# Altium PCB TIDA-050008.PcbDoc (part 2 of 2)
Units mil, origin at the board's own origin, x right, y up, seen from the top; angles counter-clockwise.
Board outline 3500 x 2500 mil, 4 copper layers (Top Layer, Signal Layer 1, Signal Layer 2, Bottom Layer), stack 38.4 mil thick; 136 components, 48 nets, 303 pads, 230 vias.
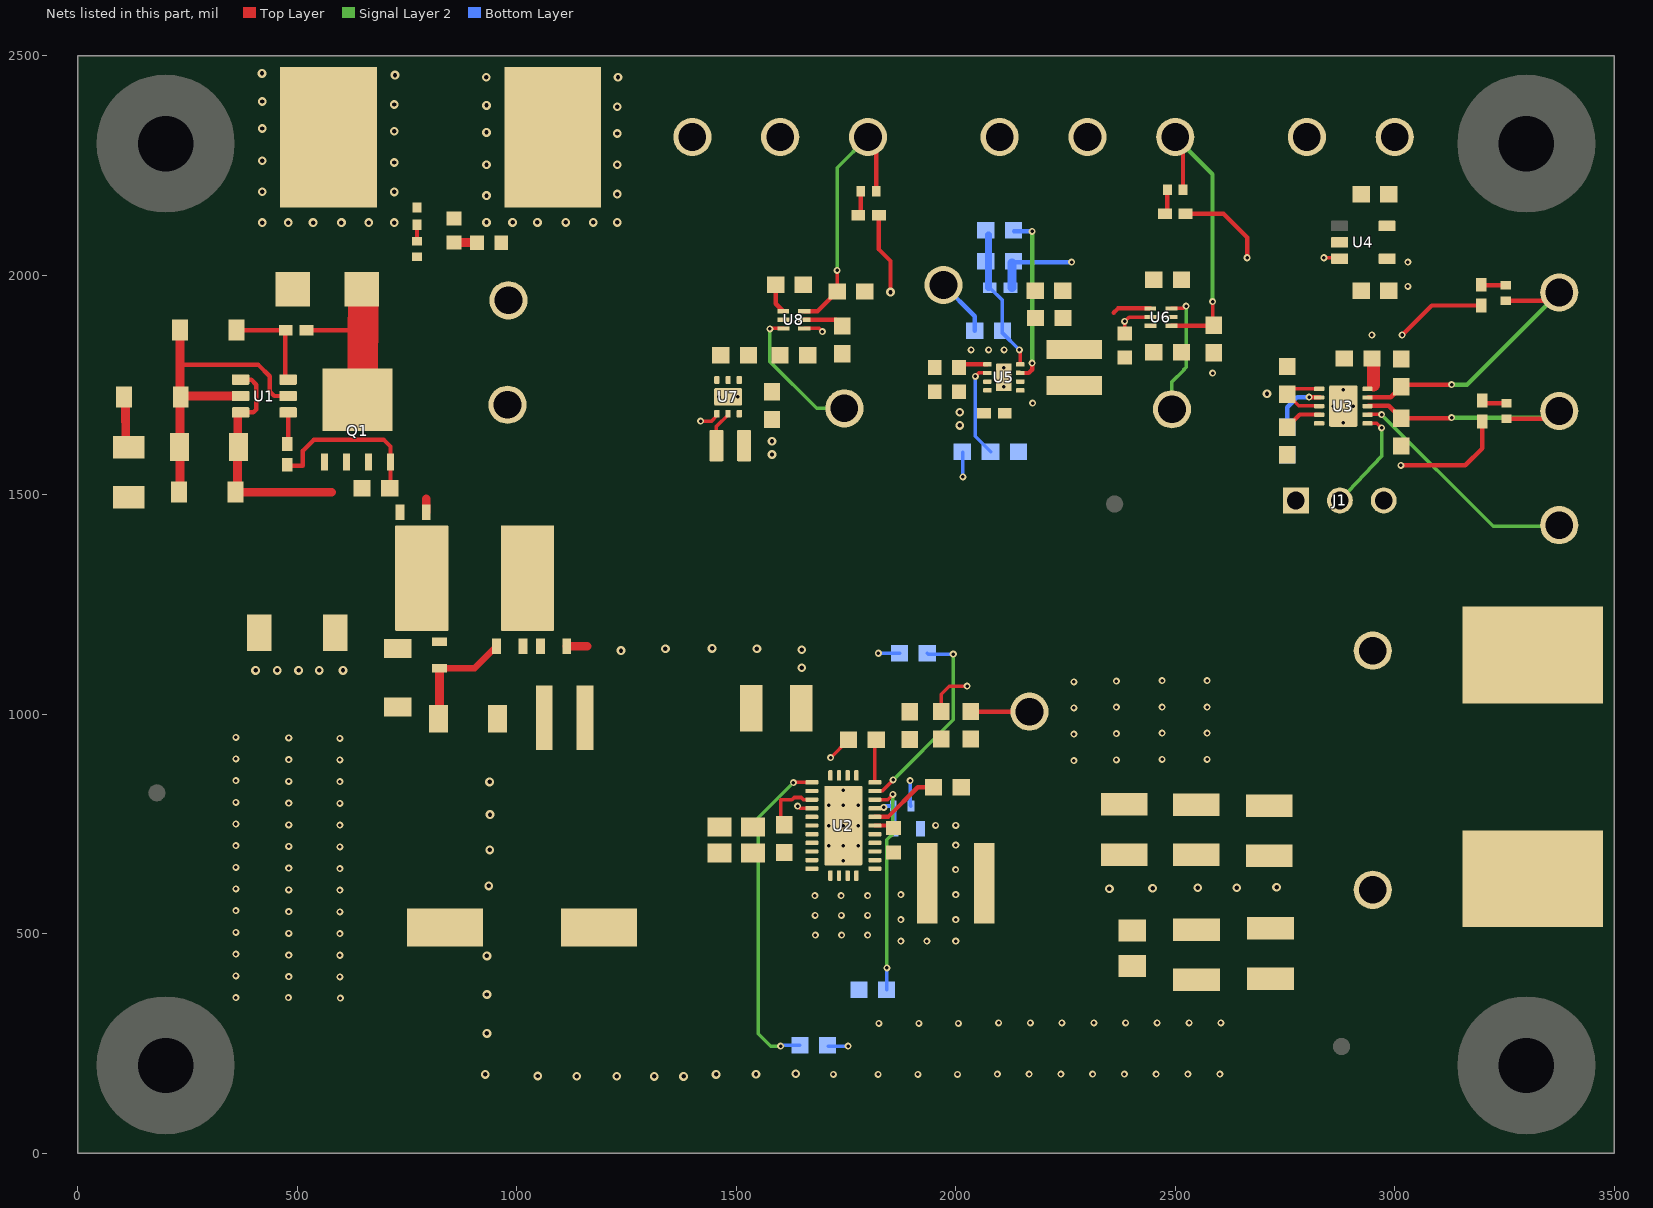
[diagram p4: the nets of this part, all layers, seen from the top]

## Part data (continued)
TP4 TP5: library part CMP-0055149-1, "Test Point, Multipurpose, White, TH", Color=White, Manufacturer=Keystone, PartNumber=5012, Supplier Part Number 1=36-5012-ND
TP6 TP13 TP17: library part CMP-0055151-1, "Test Point, Multipurpose, Yellow, TH", Color=Yellow, Manufacturer=Keystone, PartNumber=5014, Supplier Part Number 1=36-5014-ND
TP7 TP10 TP12 TP16 TP19: library part CMP-0055148-1, "Test Point, Multipurpose, Black, TH", Color=Black, Manufacturer=Keystone, PartNumber=5011, Supplier Part Number 1=36-5011-ND
TP8: library part CMP-0055150-1, "Test Point, Multipurpose, Orange, TH", Color=Orange, Manufacturer=Keystone, PartNumber=5013, Supplier Part Number 1=36-5013-ND
U1: library part CMP-0080758-2, "Automotive 40-V, microPower, Push-Pull Comparator with Shutdown, DBV0006A (SOT-23-6)", Alternate Manufacturer="Texas Instruments"
U2: library part CMP-0013936-4, "Automotive 3.5V to 36V 5A Synchronous Step-Down Voltage Regulator, RNP0030A (WQFN-30)", Alternate Manufacturer="Texas Instruments", Alternate PartNumber=LM73605QRNPTQ1
U3: library part CMP-0081417-2, "Automotive Precision Voltage Supervisor With Programmable Window Watchdog Timer, DRC0010R (VSON-10)", Alternate Manufacturer="Texas Instruments", Operating Temperature Range="-40 to 125 C", Rating=Automotive
U4: library part CMP-0081400-1, "Automotive SOT23 Precision Low Dropout Voltage Reference, DBV0005A (SOT-23-5)", Alternate Manufacturer="Texas Instruments", Alternate PartNumber=LM4132AQ1MFR2.5, Operating Temprature Range="-40 to 125 C", Rating=Automotive
U5: library part CMP-0074019-3, "3MHz, 2A Automotive Step-Down Converter in 2x2 SON Package, DSG0008A (WSON-8)", Alternate Manufacturer="Texas Instruments"
U6: library part CMP-0081404-1, "Automotive High-Accuracy Window Supervisor With Reset Time Delay and Manual Reset, DSE0006A (WSON-6)", Alternate Manufacturer="Texas Instruments"
U7: library part CMP-0065188-6, "3.5-MHz High Efficiency Step-Up Converter, DRV0006A (WSON-6)", Alternate Manufacturer="Texas Instruments"
U8: library part CMP-0081405-1, "Automotive Low-Quiescent-Current 1% Accurate Supervisor With Programmable Delay, DSE0006A (WSON-6)", Alternate Manufacturer="Texas Instruments", Operating Temprature Range="-40 to 125 C", Rating=Automotive
ZZ1: library part AssemblyNoteLabel
ZZ2 ZZ3 ZZ4: library part AssemblyNote

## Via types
v1: diameter 16, hole 8, Top Layer to Bottom Layer, 129 vias
v2: diameter 20, hole 10, Top Layer to Bottom Layer, 70 vias
v3: diameter 19.68, hole 8, Top Layer to Bottom Layer, 15 vias
v4: diameter 16, hole 8, Top Layer to Bottom Layer, tented both sides, 11 vias
v5: diameter 19.68, hole 7.87, Top Layer to Bottom Layer, 4 vias
v6: diameter 16/16/16/16 (per signal layer), hole 8, Top Layer to Bottom Layer, 1 vias

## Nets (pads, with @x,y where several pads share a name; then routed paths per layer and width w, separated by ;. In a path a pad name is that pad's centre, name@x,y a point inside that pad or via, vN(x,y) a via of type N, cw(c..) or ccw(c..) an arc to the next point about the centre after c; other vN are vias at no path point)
1.2RESET: D10.1 R10.1 TP13.1 U6.4 | length 684.6
  Top Layer w8: v1(2585,1940) 2585,1888.94 R10.1@2587,1886.94
  Top Layer w10: U6.4@2491.22,1885.16 R10.1@2586.42,1885.16 ; TP13.1@2500,2315 2517.72,2297.29 D10.1@2517.72,2195
  Signal Layer 2 w10: TP13.1@2500,2315 2585,2230 v1@2585,1942
3.3RESET: D8.1 R6.1 TP6.1 U3.9 | length 663.5
  Top Layer w10: U3.9@2940.12,1722.29 2991.18,1722.29 R6.1@3015,1746.11 3019.79,1750.9 v1(3129.77,1750.9) ; D8.1@3252.59,1942.06 3355.93,1942.06 TP6.1@3374.77,1960.9
  Signal Layer 2 w10: v1(3129.77,1750.9) 3164.77,1750.9 TP6.1@3374.77,1960.9
5.0RESET: D7.1 R12.1 TP17.1 U8.6 | length 605.3
  Top Layer w8: R12.1@1730,1963.22 v1(1730,2011)
  Top Layer w10: U8.6@1654.97,1918.27 1685.04,1918.27 R12.1@1729.85,1963.07 ; TP17.1@1800,2315 1819.06,2295.94 D7.1@1819.06,2191.77
  Signal Layer 2 w8: v1(1730,2011) 1730,2245 TP17.1@1800,2315
+1.2V: C6.1 C20.1 C21.1 C22.1 L2.2 R8.2 TP11.1 U6.1 | length 274.6
  Top Layer w10: 2360,1915 2369.53,1924.53 U6.1@2443.19,1924.53
  Bottom Layer w10: R8.2@2133.7,2030 v1(2264,2030)
  Bottom Layer w20: C20.1@2128.3,1971.46 R8.2@2128.3,2028.59
+2.5Vref: C15.1 TP9.1 U4.5
+3.3V: C11.1 C13.1 C16.1 C17.1 C18.1 C19.1 C23.1 C26.1 C28.1 CFF.1 CO1.1 CO2.1 CO3.1 CO4.1 CO5.1 CO.2 J1.1 L1.2 L3.1 P3.1 R5.2 R6.2 R7.2 R10.2 R11.2 R12.2 R15.1 R16.1 R17.1 R18.1 Rbias1.2 RFBT.2 RPG.2 TP18.1 U3.1 U3.3 U3.10 U4.3 U4.4 U5.5 U5.7 U5.8 U6.2 U7.4 U7.6 U8.4 | length 1595.7
  Top Layer w8: v1(1419,1668) 1443.93,1668 U7.4@1455.75,1679.82 ; U8.4@1654.97,1878.9 1689.22,1878.9 v1(1696.34,1871.77) ; RFBT.2@1967,1006.5 1967,1046 1985,1064 v1(2026,1064) ; C23.1@2385,1871.5 v1(2385,1895) 2394.84,1904.85 U6.2@2443.98,1904.85 ; C11.1@2755,1729.16 2781.55,1702.6 U3.3@2829.88,1702.6 ; C11.1@2767.82,1741.97 U3.1@2829.88,1741.97 ; v1(2838.91,2040) 2871.09,2040 U4.3@2873.3,2037.79
  Top Layer w10: R18.1@1824.97,2136.77 1824.97,2059.03 1851.34,2032.66 v2(1851.34,1961.77) ; C18.1@2014.35,1797.15 U5.5@2072.15,1797.15 ; R17.1@2523.62,2140 2610,2140 2664,2086 v1(2664,2040) ; v1(3014,1567) 3161,1567 3199.77,1605.77 R16.1@3199.77,1667.28 ; v1(3017,1864) 3084.15,1931.15 R15.1@3197.59,1931.15
  Top Layer w30: 2951.73,1750.52 C13.1@2951.73,1800.34
  Bottom Layer w8: RPG.2@1709.48,244 v1(1754.99,244) ; v1(1895.99,849) 1895.99,793 Rbias1.2@1897.99,791 ; v1(2016,1541) R11.2@2016,1596.62
  other v1: 2585,1777 2948,1864 3030,1975 3030,2030
  other v2: 2350,602.5 2448.5,603.5 2551.5,605 2640,605 2731,606 1581.34,1591.77 1581.34,1621.77 2009,1658 2009,1688 2709,1730
+5V: C9.2 C29.1 TP15.1 U7.2 U7.3 U8.1 | length 66.9
  Top Layer w10: C29.1@1589.85,1978.07 1589.85,1935.35 U8.1@1606.93,1918.27
AGND: CSS.2 NTGND1.2 RFBB.1 U2.19 | length 140
  Top Layer w8: v6(1639.99,790.5) 1644.62,785.87 U2.19@1672.14,785.87 ; v1(1715,901) RFBB.1@1755.68,942.2
  Bottom Layer w8: v1(1824,1139) CSS.2@1871.99,1139
AGND2: NTGND2.2 R9.1 U5.3 | length 385.4
  Top Layer w10: U5.3@2148,1777.47 2166.47,1777.47 2174,1785 v1(2174,1800)
  Signal Layer 2 w10: v1(2174,1800) v1(2174,2100)
  Bottom Layer w10: R9.1@2132.71,2100 v1(2174,2100)
BATT_SENS_PCH: D3.1 R1.1 U1.3 | length 223.6
  Top Layer w10: D3.1@361.72,1875 472.77,1875 U1.3@472.77,1762.41
BIAS: Cbias1.1 Rbias1.1 U2.8 | length 63.3
  Bottom Layer w8: v1(1835.99,788) 1838.99,791 Rbias1.1@1857.99,791 1860.49,788.5 Cbias1.1@1860.49,752
CMP_OUT_PCH: R2.1 U1.1 | length 69.8
  Top Layer w10: R2.1@479.13,1617.76 U1.1@479.13,1687.6
CRST: R7.1@2755,1654.1 U3.4 | length 86.8
  Top Layer w10: R7.1@2755,1654.1 2783.82,1682.92 U3.4@2829.88,1682.92
CT1: C10.1 U8.5 | length 72.4
  Top Layer w10: U8.5@1654.97,1898.58 C10.1@1727.33,1898.58
CT2: R7.1@2451.1,1824.85 U6.3
CWD: C12.1 U3.2 | length 129.6
  Top Layer w10: v1@2805.31,1722.29 U3.2@2829.88,1722.29
  Bottom Layer w10: C12.1@2755,1654.1 2755,1699.63 2777.97,1722.6 v1(2805,1722.6)
FB1: CFF.2 R20.2 RFBB.2 RFBT.1 U2.11 | length 98.7
  Top Layer w8: U2.11@1815.84,844.93 RFBB.2@1815.84,939.37 ; CFF.2@1892,939.5 CFF.2@1895,942.5
FB2: C20.2 R8.1 R9.2 R19.2 U5.4 | length 320.9
  Top Layer w8: U5.4@2146.95,1797.15 v1@2146.95,1828.06
  Bottom Layer w8: C20.2@2077.38,1972 2106.5,1942.88 R19.2@2106.5,1874 2106.5,1868.51 v1(2145,1830)
  Bottom Layer w15: C20.2@2074.65,1971.99 R9.2@2074.65,2091.99
FLT_GND_P: C4.2 D3.2 D4.2 D5.2 U1.2 U1.5 | length 788.1
  Top Layer w10: 234,1796 411.38,1795.87 437.25,1770 437.25,1735 447.25,1725 U1.2@472.77,1725
  Top Layer w20: D3.2@232.78,1875 D5.2@233,1505 ; D4.2@235,1725 U1.5@364.5,1725
GND: C1.2 C2.2 C3.2 C6.2 C8.2 C9.1 C10.2 C11.2 C12.2 C13.2 C15.2 C16.2 C17.2 C18.2 C19.2 C21.2 C22.2 C23.2 C25.2 C26.2 C28.2 C29.2 Cbias1.2 Cbulk1.2 CF1.2 CF2.2 CI1.1 CI2.1 CI3.2 CI4.2 CO1.2 CO2.2 CO3.2 CO4.2 CO5.2 CO.1 CVCC.2 D1.2 D6.2 J1.3 NTGND1.1 NTGND2.1 P2.1 P4.1 R3.1 R13.1 R14.1 RT.2 TP7.1 TP10.1 TP12.1 TP16.1 TP19.1 U2.12 U2.13 U2.14 U2.15 U2.17 U2.23 U2.24 U2.25 U2.26 U2.27 U2.28 U2.29 U2.30 U2.31 U3.5 U3.11 U4.2 U5.1 U5.9@2109.55,1767.62 U6.5 U7.1 U7.7@1481.34,1723.07 U8.2 | length 342.9
  Top Layer w8: U6.5@2491.22,1904.85 U6.5@2491.38,1905
  Top Layer w15: C2.2@824.01,1105 904.01,1105 C8.2@954.01,1155
  Top Layer w20: C1.2@794.01,1460 794.01,1490.99 ; CF2.2@824.01,990.04 C2.2@824.01,1105 ; C3.2@1114.01,1155 1160,1155
  other v1: 1721.5,179.5 1823,179.5 1914,179.5 2004,179.5 2095,180 2167,180 2239.5,180 2312,180 2384,180 2456.5,180 2529,180 2601.5,180 1824.99,296 1915.99,296 2005.99,296 2097.49,297 2169.99,297 2241.99,297 2314.49,297 2386.99,297 2458.99,297 2531.49,297 2603.99,297 598,353.5 360,354.5 479.5,354.5 597,401.5 480.5,402.5 360,404 480.5,451.5 597,451 360,453.5 1680.13,497.01 1740.13,497.01 1799.13,497.01 597,500.5 480.5,501 360,503 1679.5,542 1739.5,542 1799,542 480.5,550.5 597,550 360,552.5 1679.13,587.01 1739.13,587.01 1799.13,587.01 597,599.5 480.5,600 360,602 597,648.5 480.5,649.5 360,651 597,698 480.5,699 360,700.5 597,747.5 480.5,748 360,750 480.5,797.5 597,797 360,799.5 597,846.5 480.5,847 360,849 2269,894.5 480.5,896.5 597,896 2366,896 2470,897 2572.5,897 360,898.5 597,945 480.5,946 360,947.5 2269,954.5 2366,956 2470,957 2572.5,957 2269,1014.5 2366,1016 2470,1016.5 2572.5,1016.5 2269,1074 2366,1075.5 2470,1076.5 2572.5,1076.5 2175,1709 2035,1830 2075,1830 2110,1830
  other v2: 1136.51,175.5 1227.51,175.5 1313.01,175 1380.01,175 1048.01,176 928.02,179.5 1454,179.5 1545,180 1635.5,181 931.99,273 931.99,361.5 931.99,449.5 935.99,609 938.49,691 938.99,771.5 937.99,846 405,1100 454.5,1100 503,1100 550,1100 604,1100 1648.99,1106 1237.51,1145 1649,1147 1338.51,1149 1547,1149 1445.01,1150 420,2120 479.5,2120 536,2120 600.5,2120 663,2120 721,2120 420,2190.5 721,2190 721,2257 420,2261 721,2328 420,2334.5 721,2389 420,2396 722.5,2456 419.5,2460
  other v3: 1743.99,665.79 1710.52,700.83 1743.99,700.83 1777.45,700.83 1710.52,746.5 1743.99,746.5 1777.45,746.5 1710.52,792.17 1743.99,792.17 1777.45,792.17 1743.99,827.21 1459.69,1723.07 1503,1723.07 2109.55,1745.97 2109.55,1789.28
  other v4: 1875,483 1934,483 2000,483 1875,532 2000,532.03 1875,589 2000,589 2000,645.97 2000,702 1954,747 2000,747
  other v5: 2883,1664.6 2860.36,1702 2905.64,1702 2883,1739.4
L: L3.2 U7.5 | length 81.7
  Top Layer w8: L3.2@1454.85,1611.77 1454.85,1656.04 U7.5@1481.34,1682.54
LOAD_SENS_PCH: C1.1 C2.1 C4.1 CF1.1 D5.1 D6.1 FB1.1 Q1.1 Q1.2 Q1.3 R4.1 U1.4 U1.6 | length 545.6
  Top Layer w10: U1.6@364.5,1687.6 399.85,1687.6 406.43,1694.18 406.43,1750.83 394.85,1762.41 U1.4@364.5,1762.41
  Top Layer w20: D5.1@363.25,1506 578.25,1506 ; D5.1@364,1505 U1.6@364.5,1687.6
MODE: R11.1 R13.2 U5.6 | length 217.7
  Top Layer w8: v1(2044.55,1769.91) 2052.11,1777.47 U5.6@2072.15,1777.47
  Bottom Layer w8: v1(2044.55,1769.91) 2044.55,1633.08 R13.2@2080,1597.62
MR1: TP3.1 U8.3 | length 319.2
  Top Layer w8: v1@1577.17,1878.9 U8.3@1607.72,1878.9
  Signal Layer 2 w8: v1(1576.34,1878.07) 1576.34,1803.64 1683.22,1696.77 TP3.1@1746.34,1696.77
MR2: TP14.1 U6.6 | length 285.1
  Top Layer w8: U6.6@2491.22,1924.53 2519.53,1924.53 v1(2525,1930)
  Signal Layer 2 w8: TP14.1@2492.6,1694.85 2492.6,1757.09 2520.6,1785.09 2520,1785.69 2525,1790.69 v1(2525,1930)
NetC3_1: C3.1 C8.1 CF2.1 FB1.2 LF1.1
NetC24_1: C24.1 C25.1 | length 52
  Top Layer w20: C25.1@857,2074.44 C24.1@909,2074.44
NetCB_1: CB.1 U2.6 | length 39.2
  Top Layer w10: U2.6@1815.84,746.5 CB.1@1855.06,746.5
NetD2_2: D2.2 R14.2 | length 42.6
  Top Layer w10: D2.2@772.8,2077.59 R14.2@772.8,2120.19
NetD4_1: D4.1 R3.2 | length 109.9
  Top Layer w20: D4.1@108.78,1717.89 R3.2@109,1608
NetD7_2: D7.2 R18.2 | length 49.1
  Top Layer w10: R18.2@1783.63,2142.68 D7.2@1783.63,2191.77
NetD8_2: D8.2 R15.2 | length 54.1
  Top Layer w10: R15.2@3198.49,1977.49 D8.2@3252.59,1977.49
NetD9_2: D9.2 R16.2 | length 49.1
  Top Layer w10: R16.2@3205.68,1708.61 D9.2@3254.77,1708.61
NetD10_2: D10.2 R17.2 | length 49.1
  Top Layer w10: R17.2@2482.28,2145.91 D10.2@2482.28,2195
NetRPG_1: RPG.1 U2.16 | length 754.2
  Top Layer w8: v1(1629.99,844) 1630.91,844.93 U2.16@1672.14,844.93
  Signal Layer 2 w8: v1@1605.49,244 1578.49,244 1550.49,272 1550.49,358 1550.49,764.5 v1(1629.99,844)
  Bottom Layer w8: v1@1605.49,244 1606.99,245.5 RPG.1@1644.99,245.5
  other v1: 1601,244
P_Gate: Q1.4 R2.2 R4.2 | length 364.8
  Top Layer w10: R2.2@479.63,1565.75 512.25,1565.75 512.25,1600 537.25,1625 697.25,1625 712.25,1610 Q1.4@712.25,1574.57 R4.2@712.25,1528.63
RT: RT.1 U2.9 | length 496.9
  Top Layer w8: U2.9@1815.84,805.56 1845.04,805.56 v1(1856.99,817.5)
  Signal Layer 2 w8: v1(1843,422) 1843,714.19 1856.99,728.17 v1(1856.99,817.5)
  Bottom Layer w8: RT.1@1843,372.5 v1(1843,422)
SET1: J1.2 U3.6 | length 237.7
  Top Layer w8: U3.6@2940.12,1663.23 2959.37,1663.23 v1(2970,1652.6)
  Signal Layer 2 w8: J1.2@2875,1487 2970,1587.6 v1(2970,1652.6)
SS/TRK: CSS.1 U2.10 | length 455.9
  Top Layer w8: U2.10@1815.84,825.24 1832.45,825.24 v1(1857.49,850.27)
  Signal Layer 2 w8: v1(1857.49,850.27) 1994.33,987.12 v1(1994.33,1137)
  Bottom Layer w8: v1(1857.49,850.27) v1@1857.72,850.5 ; CSS.1@1934.98,1139 1936.98,1137 v1(1994.33,1137)
SW: CB.2 L1.1 U2.1 U2.2 U2.3 U2.4 U2.5
SW2: L2.1 U5.2
V_CTRL1: R20.1 TP5.1 | length 133.5
  Top Layer w10: R20.1@2034.5,1006 TP5.1@2168,1006
V_CTRL2: R19.1 TP4.1 | length 133.6
  Bottom Layer w10: TP4.1@1972,1978 2043.5,1906.5 R19.1@2043.5,1874
VBATT_PCH: C24.2 D1.1 D2.1 P1.1 Q1.5 R1.2 TP2.1 | length 362.7
  Top Layer w10: R1.2@520.87,1875 648.74,1875
  Top Layer w70: Q1.5@648.74,1728.19 D1.1@650,1963
  other v2: 931,2120.5 990.5,2120.5 1047,2120.5 1111.5,2120.5 1174,2120.5 1229,2120.5 931,2181.5 1229,2185 931,2252 1229,2252 1229,2323 931,2325.5 1229,2384 931,2387 930.5,2451 1230.5,2451
VCC: CVCC.1 U2.7 | length 161.8
  Top Layer w10: U2.7@1815.84,766.19 1845.92,766.19 1913.73,834 CVCC.1@1949.5,834
VIN1: Cbulk1.1 CI1.2 CI2.2 CI3.1 CI4.1 LF1.2 U2.18 U2.20 U2.21 U2.22 | length 136
  Top Layer w8: CI1.2@1608.99,748 1600.99,756 1600.99,805.56 1626.94,805.56 1631.76,810.37 1648.22,810.37 1653.04,805.56 U2.18@1672.14,805.56
WDI: TP1.1 U3.7 | length 539.7
  Top Layer w8: U3.7@2940.12,1682.92 v1@2969.69,1682.92
  Signal Layer 2 w8: v1(2970,1682.6) 3224.3,1428.3 TP1.1@3374.81,1428.3
WDO: D9.1 R5.1 TP8.1 U3.8 | length 557
  Top Layer w10: U3.8@2940.12,1702.6 2986.5,1702.6 R5.1@3015,1674.1 v1@3127.97,1674.1 ; D9.1@3254.77,1673.18 3357.06,1673.18 TP8.1@3374.77,1690.9
  Signal Layer 2 w10: v1(3129.77,1675.9) TP8.1@3359.77,1675.9
pads on no net: FID1.1 FID2.1 FID3.1 H1.1 H2.1 H3.1 H4.1 U2.31A U4.1 U5.9@2109.55,1749.91 U5.9@2109.55,1785.34 U7.7@1463.63,1723.07 U7.7@1499.06,1723.07

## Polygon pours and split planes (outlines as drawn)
+2.5Vref on Top Layer "TOP_LAYER_+2.5VREF_P060" (solid, remove dead copper, pour order 60): 2970,2190 3005,2190 3005,2220 3020,2230 3075,2275 3075,2390 2925,2390 2925,2265 2970,2220
+3.3V on Top Layer "TOP_LAYER_+3.3V_P055" (solid, remove dead copper, pour order 55): 2080,1760 2065,1760 2060,1750 1994.12,1750 1994.12,1645 2080,1645
NetC3_1 on Top Layer "TOP_LAYER_NETC3_1_P057" (solid, remove dead copper, pour order 57): 1005.01,1335 1005.01,1105 935.01,1035 935,899 1074,899 1074,1335
+1.2V on Top Layer "TOP_LAYER_+1.2V_P061" (solid, remove dead copper, pour order 61): 2225,1820 2225,1833.91 2225,2390 2375,2390 2375,1910.82 2325,1860.82 2325,1820
+5V on Top Layer "TOP_LAYER_+5V_P059" (solid, remove dead copper, pour order 59): 1446.34,1751.77 1486.34,1751.77 1486.34,1836.77 1486.34,1886.77 1606.34,1966.77 1671.34,2026.77 1671.34,2390 1531.34,2390 1531.34,2116.77 1446.34,2031.77
VBATT_PCH on Top Layer "TOP_LAYER_VBATT_PCH_P058" (solid, remove dead copper, pour order 58): 905,2530 905,2048 650,2048 650,1820 1060,1820 1255,2015 1255,2530
+3.3V on Top Layer "TOP_LAYER_+3.3V_P062" (solid, remove dead copper, pour order 62): 2043,478.69 2043,709 2934,709 2991.01,766 3474.52,766 3474.52,479.31
SW2 on Top Layer "TOP_LAYER_SW2_P056" (solid, remove dead copper, pour order 56): 2146.95,1762.46 2146.95,1752.46 2180.37,1752.46 2207.37,1729.47 2315,1729.47 2315,1769 2198.02,1769 2180.37,1762.46
SW on Top Layer "TOP_LAYER_SW_P054" (solid, remove dead copper, pour order 54): 1800.61,706 1958,706 1958,538 1913,538 1913,645 1800.61,645
VIN1 on Top Layer "TOP_LAYER_VIN1_P049" (solid, remove dead copper, pour order 49): 1609.5,774.79 1145,774.79 1145,719.5 1609.01,719.5
VIN1 on Top Layer "TOP_LAYER_VIN1_P050" (solid, pour order 50): 1585.61,774.22 1675.77,774.72 1675.77,719.28 1585.61,719.28
GND on Top Layer "TOP_LAYER_GND_P065" (solid, remove dead copper, pour order 65): 20,2480 20,19 3486,19 3486,2480
LOAD_SENS_PCH on Top Layer "TOP_LAYER_LOAD_SENS_PCH_P053" (solid, remove dead copper, pour order 53): 555,1593 555,1131 844,1131 844,1429 843,1430 767.43,1430 744,1453.43 744,1478.68 677.32,1478.68 669,1487 669,1593
VIN1 on Top Layer "TOP_LAYER_VIN1_P052" (solid, remove dead copper, pour order 52): 1138.61,1063 1138.61,473 1224,473 1224,1063
VIN1 on Top Layer "TOP_LAYER_VIN1_P051" (solid, remove dead copper, pour order 51): 1534.35,1063 1156.85,1063 1156.85,968 1533.5,968
GND on Signal Layer 2 "SIGNAL_LAYER_2_GND_P067" (solid, remove dead copper, pour order 67): 0,2500 0,0 3500,0 3500,2500
+3.3V on Signal Layer 2 "SIGNAL_LAYER_2_+3.3V_P064" (solid, remove dead copper, pour order 64): 1389,2058 3145,2058 3145,150 1389,150
AGND on Signal Layer 2 "SIGNAL_LAYER_2_AGND_P063" (solid, pour order 63): 1632.09,778.69 1632.09,810.01 1699.59,877.51 1700.42,1172.49 1892.81,1171.99 1892.81,1016.29 1699.53,823.01 1673.03,796.51 1673.03,779.27
GND on Bottom Layer "BOTTOM_LAYER_GND_P068" (solid, remove dead copper, pour order 68): 0,2500 0,0 3500,0 3500,2500
GND on Signal Layer 1 "SIGNAL_LAYER_1_GND_P066" (solid, remove dead copper, pour order 66): 0,2500 0,0 3500,0 3500,2500

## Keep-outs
Signal Layer 1:
  rectangle: 630,890 1138.61,1479
Signal Layer 2:
  rectangle: 630,890 1138.61,1479
Bottom Layer:
  rectangle: 630,890 1138.61,1479
Keep-Out Layer:
  the board outline again, w10
  text ".Layer_Name" at 277,-928.49 h60

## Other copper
Top Layer:
  rectangle net +3.3V: 3001.73,1552.52 3027,1620.93
  rectangle net +3.3V: 3000.73,1795.52 3033,1885.9
  rectangle net +3.3V: 1778,1946.77 1866.34,1976.77
  rectangle net +3.3V: 2690.78,1712.6 2755.21,1746
  rectangle net +2.5Vref: 2971.33,2104.25 3000,2185
  region net +3.3V: 2600,1761 2600,1832.42 2570,1832.42 2570,1761
  rectangle net +3.3V: 2504.25,1810 2606.3,1840
  rectangle net CT2: 2437.09,1824.85 2454.55,1885
  rectangle net +1.2V: 2435,1924.53 2455.79,1990
  rectangle net +3.3V: 2738.68,1456.63 2810,1595
  rectangle net +3.3V: 2970,1950 3045,2050
  rectangle net +3.3V: 1996.95,1727.78 2016.95,1795.73
  rectangle net +3.3V: 1646.34,1818.07 1665.77,1881.77
  rectangle net +3.3V: 1874.99,987 1988.49,1028
  rectangle net FB1: 1797.99,917.32 2052.7,967
  rectangle net +3.3V: 2936.73,1795.52 2938.39,1825.52
  rectangle net +3.3V: 2931.73,1795.52 2964,1885.9
  rectangle net +3.3V: 1501.34,1576.77 1605.75,1694.68
  rectangle net GND: 637,986 839,1024
  rectangle net SW: 1802,707.13 1830,731
  pour cut-out: 770.41,1440 753.01,1457.4 753.01,1486.5 1126.5,1486.5 1143,1470 1143,890 1073.14,890 1074.18,1180.71 1086.48,1180.71 1093.28,1187.52 1093,1440
  pour cut-out: 853.06,1428 853.06,1143.49 848.1,1138.52 653.06,1138.52 652.59,1139 651.59,1138 651.59,890 926.41,890 926.41,915 926.41,1050 929.92,1058.31 996.41,1124.8 995.59,1125.62 995.59,1196.71 961.88,1196.71 949.25,1209.33 949.25,1428
  pour cut-out: 1472.96,1646.22 1472,1567 1501.92,1567 1498,1571 1498,1646.22
  pour cut-out: 2341.99,1801.7 2205.23,1803.34 2205.23,1773.42 2209.23,1777.34 2341.99,1777.34
  text ".Layer_Name" at 277,-928.49 h60
Bottom Layer:
  text ".Layer_Name" at 277,-928.49 h60

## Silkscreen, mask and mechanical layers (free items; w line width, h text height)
Top Overlay:
  region: 2857,1275 2557,1275 2557,1175 2857,1175
  lines w5: 1715,2469 1902,2469 ; 2436,2469 2648,2469 ; 3243,2111 3466,2111 ; 3324,1855 3433,1855
  text "'.PRJ_Number'.PCB_Rev-" at 2133.63,1292.21 h108.27
  text ".Layer_Name" at 277,-928.49 h60
Bottom Overlay:
  text ".Layer_Name" at 277,-928.49 h60
Top Paste:
  text ".Layer_Name" at 277,-928.49 h60
Bottom Paste:
  text ".Layer_Name" at 277,-928.49 h60
Top Solder:
  text ".Layer_Name" at 277,-928.49 h60
  text ".Layer_Name" at 277,-928.49 h60
Bottom Solder:
  text ".Layer_Name" at 277,-928.49 h60
Drill Guide:
  text ".Layer_Name" at 277,-928.49 h60
M1 Board Outline:
  the board outline again, w10
  text ".Layer_Name" at 277,-928.49 h60
M2 Board Dimensions:
  rectangle: -300,-345 -175,-220
  rectangle: -175,-470 200,-345
  lines w7: -300,-345 700,-345 ; -175,-470 -175,-220 ; -50,-470 -50,-220 ; 200,-470 200,-220 ; 450,-470 450,-220 ; -300,-470 700,-470 700,-220 -300,-220 -300,-470
  text ".Layer_Name" at 277,-928.49 h60
M3 3D STEP Top:
  text ".Layer_Name" at 277,-928.49 h60
M4 3D STEP Bottom:
  text ".Layer_Name" at 277,-928.49 h60
M5 Assembly Top:
  lines w10: -592,-1000.16 6008,-1000.16 ; -592,-796.83 6010,-796.83 ; -592,-593.5 -592,-1203.5 3413,-1203.5 6010,-1203.5 6010,-593.5 -591.5,-593.5 -591.5,-1203.5 984,-1203.5 ; 1873,-1203.5 1873,-593.5 ; 3140,-796.83 3140,-593.5 ; 3980,-796.83 3980,-593.5 ; 4602,-1210 4602,-1007.16
  text "COMPONENTS MARKED 'DNP' SHOULD NOT BE POPULATED." at 853.5,-388.5 h60
  text "ASSEMBLY VARIANT:" at 853,-504 h60
  text ".VariantName" at 1889,-504 h60
  text "PCB VIEWED FROM TOP SIDE" at -528.5,-725.66 h60
  text "BOARD #:" at 1948,-725.66 h60
  text ".PRJ_Number" at 2493.5,-725.66 h60
  text "REV:" at 3338,-725.66 h60
  text ".PCB_Rev" at 3629.5,-725.66 h60
  text "SVN REV:" at 4176,-725.66 h60
  text ".VersionControl_RevNumber" at 4682,-725.66 h60
  text "TID #:" at 1948,-929 h60
  text ".TID" at 2493.5,-929 h60
  text "PLOT NAME =" at -528.5,-1134.33 h60
  text ".plot_File_Name" at 277,-1134.33 h60
  text "GENERATED    :" at 1950,-1134.33 h60
  text ".Print_Date" at 2819.5,-1134.33 h60
  text ".Print_Time" at 3548.5,-1134.33 h60
  text "TEXAS INSTRUMENTS" at 4813,-1134.33 h60
M6 Assembly Bottom:
  lines w10: -592.5,-797.33 6009.5,-797.33 ; -590.5,-1000.66 6009.5,-1000.66 ; 815.5,-1210.5 815.5,-1007.66 ; 1437.5,-797.33 1437.5,-594 ; 2277.5,-797.33 2277.5,-594 ; 3544.5,-1204 3544.5,-594 ; 4433.5,-1204 6009,-1204 6009,-594 -592.5,-594 -592.5,-1204 2004.5,-1204 6009.5,-1204 6009.5,-594
  text "COMPONENTS MARKED 'DNP' SHOULD NOT BE POPULATED." at 5802,-388 h60
  text ".VariantName" at 4758,-504 h60
  text "ASSEMBLY VARIANT:" at 5797,-504 h60
  text ".VersionControl_RevNumber" at 735.5,-726.16 h60
  text "SVN REV:" at 1241.5,-726.16 h60
  text ".PCB_Rev" at 1788,-726.16 h60
  text "REV:" at 2079.5,-726.16 h60
  text ".PRJ_Number" at 2924,-726.16 h60
  text "BOARD #:" at 3469.5,-726.16 h60
  text "PCB VIEWED FROM BOTTOM SIDE" at 5946,-726.16 h60
  text ".TID" at 2924,-929.5 h60
  text "TID #:" at 3469.5,-929.5 h60
  text "TEXAS INSTRUMENTS" at 604.5,-1134.83 h60
  text ".Print_Time" at 1869,-1134.83 h60
  text ".Print_Date" at 2598,-1134.83 h60
  text "GENERATED    :" at 3467.5,-1134.83 h60
  text ".plot_File_Name" at 5140.5,-1134.83 h60
  text "PLOT NAME =" at 5946,-1134.83 h60
M9 Title Sheet:
  drawing of 57 lines, arcs and shapes, not listed
  text "1" at 439.84,7966.5 h70
  text "2" at 2935.5,7966.5 h70
  text "3" at 5424.84,7966.5 h70
  text "4" at 7931.51,7966.5 h70
  text "5" at 10430.5,7966.5 h70
  text "6" at 12935.5,7966.5 h70
  text "A" at -716.5,6823.5 h70
  text "A" at 14083.5,6823.5 h70
  text "B" at -716.5,4443.5 h70
  text "B" at 14083.5,4443.5 h70
  text "C" at -716.5,2068.5 h70
  text "C" at 14083.5,2068.5 h70
  text "PROJECT TITLE:" at 11043.5,207.5 h45
  text ".PRJ_Title" at 11093.5,74.18 h70
  text "DESIGNED FOR:" at 11043.5,-93.5 h45
  text ".PRJ_Customer" at 11093.5,-233.5 h70
  text "D" at -716.5,-301.5 h70
  text "D" at 14083.5,-301.5 h70
  text "FILE NAME:" at 11043.5,-393.5 h45
  text ".PCB_File_Name_No_Path" at 11093.5,-513.5 h70
  text "Texas Instruments (TI) and/or its licensors do not warrant the accuracy or completeness of this specification" at 6074,-675.33 h45
  text "ENGINEER:" at 11043.5,-683.5 h45
  text "LAYOUT BY:" at 12548.5,-683.5 h45
  text "or any information contained therein. TI and/or its licensors do not warrant that this design will meet" at 6029.01,-788 h45
  text ".PRJ_Engineer" at 11093.5,-838.49 h70
  text ".PCB_Layout" at 12599,-838.49 h70
  text "the specifications, will be suitable for your application or fit for any particular purpose, or will operate in" at 6029.01,-900.67 h45
  text ".Layer_Name" at 277,-928.49 h60
  text "ALTIUM DESIGNER VERSION:" at 12548.5,-993.5 h45
  text "an implementation. TI and/or its licensors do not warrant that the design is production worthy. You should" at 6029.01,-1013.33 h45
  text "completely validate and test your design implementation to confirm the system functionality for your application." at 6074,-1126 h45
  text ".print_Scale" at 11093.5,-1126.82 h70
  text ".Application_BuildNumber" at 12599,-1126.82 h70
  text "1" at 439.84,-1333.5 h70
  text "2" at 2935.5,-1333.5 h70
  text "3" at 5424.84,-1333.5 h70
  text "4" at 7931.51,-1333.5 h70
  text "5" at 10430.5,-1333.5 h70
  text "6" at 12935.5,-1333.5 h70
M10 Fab Notes:
  drawing of 189 lines, arcs and shapes, not listed
  text "DESIGN INFORMATION" at 12082.02,6286.18 h60
  text "MIN. TRACK WIDTH:" at 11437.46,6154.05 h60
  text "6" at 12533.7,6154.06 h60
  text "MIL" at 12688.46,6154.05 h60
  text "MIN. CLEARANCE:" at 11437.46,6029.93 h60
  text "5" at 12532,6030 h60
  text "MIL" at 12688.46,6029.93 h60
  text "MIN. VIA PAD SIZE:" at 11437.46,5905.8 h60
  text "16" at 12503.71,5905.8 h60
  text "MIL" at 12688.46,5905.8 h60
  text "0.1mm (4 MIL)" at 12132.46,5775.9 h60
  text "MINIMUM ANNULAR RING" at 11108.23,5767.68 h60
  text "EXTERNAL" at 12840.46,5767.68 h60
  text "PER" at 11308.23,5657.55 h60
  text "IPC-D-275 CLASS 2 LEVEL C" at 11528.23,5657.55 h60
  text "MIL, HOLES" at 13016.46,5557.07 h60
  text "+/-" at 12624,5548.49 h60
  text "+/-" at 13478,5548.49 h60
  text "REGISTRATION TOLERANCES:" at 11108.23,5547.42 h60
  text "METAL" at 12308,5547.42 h60
  text "5" at 12884.2,5547.43 h60
  text "3" at 13717.2,5547.43 h60
  text "MIL" at 13833.46,5547.42 h60
  text "HOLE SIZE TOLERANCE (UNLESS OTHERWISE SPECIFIED):" at 11108.23,5449.11 h60
  text "+/-" at 13478,5446.23 h60
  text "3" at 13717.2,5445.17 h60
  text "MIL" at 13833.46,5445.17 h60
  text "MATERIAL:" at 11033.46,5307.52 h60
  text "FR-4 High Tg" at 12019.9,5179 h60
  text "X" at 11875.46,5171.01 h60
  text "FR-408" at 11454.46,5166.49 h60
  text "OTHER" at 12942.46,5166.49 h60
  text "62 MIL (1.6mm) +/-10%" at 11774.56,5023.46 h60
  text "X" at 11654.46,5021.01 h60
  text "THICKNESS:" at 11108.23,5015.24 h60
  text "OTHER" at 13059.46,5015.24 h60
  text "TOLERANCE:" at 11108.23,4876.93 h60
  text "X" at 11956.46,4876.93 h60
  text "ANSI IPC-6012 TYPE 3 CLASS 2" at 12134.48,4876.93 h60
  text "OTHER +/-" at 12134.46,4732.74 h60
  text "BOW & TWIST:" at 11108.23,4587.55 h60
  text "X" at 11956.46,4587.55 h60
  text "ANSI IPC-6012 TYPE 3 CLASS 2" at 12134.48,4587.55 h60
  text "OTHER +/-" at 12134.46,4440.85 h60
  text "DRILLING:" at 11033.46,4310.23 h60
  text "NC_DRILL FILES" at 12794.46,4205.04 h60
  text "REFERENCE:" at 11108.23,4201.11 h60
  text "X" at 11765.46,4201.01 h60
  text "AS SHOWN" at 11943.46,4201.11 h60
  text "X" at 12666.46,4201.11 h60
  text "OTHER" at 13092.46,4058.86 h60
  text "PTH COPPER THICKNESS:" at 11107.91,4055.33 h60
  text "X" at 12247.14,4055.33 h60
  text "20-30 um" at 12375.14,4055.33 h60
  text "BOARD FINISH:" at 11033.46,3907.73 h60
  text "SILKSCREEN:" at 11188.68,3797.6 h60
  text "X" at 12146.46,3797.6 h60
  text "TOP" at 12263.46,3797.6 h60
  text "X" at 12656.46,3797.6 h60
  text "BOTTOM" at 12774.46,3797.6 h60
  text "SILKSCREEN COLOR:" at 11188.68,3642.41 h60
  text "X" at 12145.46,3642.41 h60
  text "WHITE" at 12263.46,3642.41 h60
  text "OTHER" at 12774.46,3642.41 h60
  text "X" at 12276.46,3498.97 h60
  text "GREEN" at 12394.46,3498.97 h60
  text "OTHER" at 13012.46,3498.97 h60
  text "SOLDER RESIST COLOR:" at 11188.68,3492.1 h60
  text "X" at 12276.46,3344.71 h60
  text "MATTE" at 12394.46,3344.71 h60
  text "SEMI-GLOSS" at 13012,3344.08 h60
  text "IMMERSION GOLD (ENIG)" at 12094.46,3171.94 h60
  text "ENEPIG" at 13432,3164.72 h60
  text "SURFACE FINISH:" at 11033.46,3163.72 h60
  text "X" at 11916.46,3163.72 h60
  text "IMM. TIN/SILVER OR EQUIV" at 11363,3026.41 h60
  text "OTHER" at 12794.46,3022.47 h60
  text "ARRAY/PANEL:" at 11033.46,2867.09 h60
  text "CUT AND TRIM PER M1 BOARD OUTLINE" at 12094.46,2858.87 h60
  text "X" at 11910,2850 h60
  text "N.C. ROUTE" at 12094.46,2722.9 h60
  text "V. SCORE" at 12960.46,2722.9 h60
  text "CERTIFICATION:" at 11033.46,2593.78 h60
  text "MATERIALS AND WORKMANSHIP FOR ALL PCBS" at 11758.46,2593.78 h60
  text "TO MEET OR EXCEED THE REQUIREMENTS OF:" at 11758.46,2499.71 h60
  text "X" at 11395.97,2371.08 h60
  text "ANSI IPC-A-600F CLASS ->" at 11523.96,2371.08 h60
  text "X" at 13171.97,2371.08 h60
  text "2" at 13281.96,2371.08 h60
  text "1" at 12966.96,2369.59 h60
  text "3" at 13635.96,2369.59 h60
  text "X" at 12207.97,2223.4 h60
  text "RoHS" at 12335.96,2223.4 h60
  text "OTHER" at 12980.36,2223.4 h60
  text "PER ORDER" at 13377.42,2223.4 h60
  text "ALL BOARDS MUST MEET OR EXCEED UL94-V0 REQUIREMENTS." at 11061,2069.57 h60
  text "PCB MUST BEAR THE UL94V-0 UL REGISTERED MATERIAL ID NUMBER" at 11061,1953.51 h60
  text "ADDITIONAL REQUIREMENTS:" at 11033.46,1784.08 h60
  text "MICROSECTION:" at 11108.23,1676.96 h60
  text "YES" at 12013.96,1676.96 h60
  text "REQUIRED" at 12875.46,1532.62 h60
  text "BARE BOARD ELEC. TEST:" at 11108.23,1529.77 h60
  text "NONE" at 12413.96,1529.77 h60
  text "X" at 12757.46,1529.77 h60
  text "PER ORDER" at 13467.46,1529.77 h60
  text "XX MIL VIAS REQUIRE NON-CONDUCTIVE FILL AND PLANARIZE" at 11276.38,1324.82 h59
  text "XX MIL VIAS REQUIRE CONDUCTIVE FILL AND PLANARIZE" at 11284.38,1220.85 h60
  text "OUTER XX MIL VIAS REQUIRE 50 OHM SINGLE-ENDED IMPEDANCE" at 11283.39,1057.46 h58
  text "LAYER 2 & 3 (INNER LAYERS) XX MIL WIDE, XX MIL SPACE / TRACES REQUIRE 100 OHM DIFFERENTIAL IMPEDANCE" at 11275.39,821.75 h60
  text ".Layer_Name" at 5720.76,266.01 h60
  text ".Layer_Name" at 277,-928.49 h60
M11 Gerber Information:
  lines w10: -592,-1000.16 6008,-1000.16 ; -592,-796.83 6010,-796.83 ; -592,-593.5 -592,-1203.5 3413,-1203.5 6010,-1203.5 6010,-593.5 -591.5,-593.5 -591.5,-1203.5 984,-1203.5 ; 1873,-1203.5 1873,-593.5 ; 3140,-796.83 3140,-593.5 ; 3980,-796.83 3980,-593.5 ; 4602,-1210 4602,-1007.16
  text "ALL ARTWORK VIEWED FROM TOP SIDE" at -528.5,-725.66 h60
  text "BOARD #:" at 1948,-725.66 h60
  text ".PRJ_Number" at 2493.5,-725.66 h60
  text "REV:" at 3338,-725.66 h60
  text ".PCB_Rev" at 3629.5,-725.66 h60
  text "SVN REV:" at 4176,-725.66 h60
  text ".VersionControl_RevNumber" at 4682,-725.66 h60
  text "LAYER NAME =" at -528.5,-928.49 h60
  text "TID #:" at 1948,-929 h60
  text ".TID" at 2493.5,-929 h60
  text "PLOT NAME =" at -528.5,-1134.33 h60
  text ".plot_File_Name" at 277,-1134.33 h60
  text "GENERATED    :" at 1950,-1134.33 h60
  text ".Print_Date" at 2819.5,-1134.33 h60
  text ".Print_Time" at 3548.5,-1134.33 h60
  text "TEXAS INSTRUMENTS" at 4813,-1134.33 h60
M12 Stackup:
  drawing of 295 lines, arcs and shapes, not listed
  text "Layer" at 9497.84,7760 h60
  text "Name" at 9907.76,7760 h60
  text "Material" at 10847.5,7760 h60
  text "Thickness" at 11707.26,7760 h60
  text "Constant" at 12357.1,7760 h60
  text "Board Layer Stack" at 12926.96,7760 h60
  text "1" at 9497.84,7640 h60
  text "Top Overlay" at 9907.76,7640 h60
  text "2" at 9497.84,7520 h60
  text "Top Solder" at 9907.76,7520 h60
  text "Solder Resist" at 10847.5,7520 h60
  text "0.40mil" at 11707.26,7520 h60
  text "3.5" at 12357.1,7520 h60
  text "3" at 9497.84,7400 h60
  text "Top Layer" at 9907.76,7400 h60
  text "Copper" at 10847.5,7400 h60
  text "2.80mil" at 11707.26,7400 h60
  text "4" at 9497.84,7280 h60
  text "Dielectric1" at 9907.76,7280 h60
  text "FR-4" at 10847.5,7280 h60
  text "10.00mil" at 11707.26,7280 h60
  text "4.2" at 12357.1,7280 h60
  text "5" at 9497.84,7160 h60
  text "Signal Layer 1" at 9907.76,7160 h60
  text "Copper" at 10847.5,7160 h60
  text "1.40mil" at 11707.26,7160 h60
  text "6" at 9497.84,7040 h60
  text "Dielectric 2" at 9907.76,7040 h60
  text "FR-4" at 10847.5,7040 h60
  text "10.00mil" at 11707.26,7040 h60
  text "4.2" at 12357.1,7040 h60
  text "7" at 9497.84,6920 h60
  text "Signal Layer 2" at 9907.76,6920 h60
  text "Copper" at 10847.5,6920 h60
  text "1.40mil" at 11707.26,6920 h60
  text "8" at 9497.84,6800 h60
  text "Dielectric3" at 9907.76,6800 h60
  text "FR-4" at 10847.5,6800 h60
  text "10.00mil" at 11707.26,6800 h60
  text "4.2" at 12357.1,6800 h60
  text "9" at 9497.84,6680 h60
  text "Bottom Layer" at 9907.76,6680 h60
  text "Copper" at 10847.5,6680 h60
  text "2.80mil" at 11707.26,6680 h60
  text "10" at 9497.84,6560 h60
  text "Bottom Solder" at 9907.76,6560 h60
  text "Solder Resist" at 10847.5,6560 h60
  text "0.40mil" at 11707.26,6560 h60
  text "3.5" at 12357.1,6560 h60
  text "11" at 9497.84,6440 h60
  text "Bottom Overlay" at 9907.76,6440 h60
  text ".Layer_Name" at 277,-928.49 h60
M13 Component Bodies Top:
  text ".Layer_Name" at 277,-928.49 h60
M14 Component Bodies Bottom:
  text ".Layer_Name" at 277,-928.49 h60
M15 Courtyards Top:
  text ".Layer_Name" at 277,-928.49 h60
M16 Courtyards Bottom:
  text ".Layer_Name" at 277,-928.49 h60
Drill Drawing:
  circle w10: c4459.76,2551.3 r27.63
  lines w10: 4432.13,2703.26 4487.39,2703.26 4459.76,2648 4432.13,2703.26 ; 4432.13,2772.34 4487.39,2772.34 4487.39,2827.6 4432.13,2827.6 4432.13,2772.34 ; 4432.13,2910.49 4445.95,2910.49 4445.95,2896.67 4473.58,2896.67 4473.58,2910.49 4487.39,2910.49 4487.39,2938.12 4473.58,2938.12 4473.58,2951.93 4445.95,2951.93 4445.95,2938.12 4432.13,2938.12 4432.13,2910.49 ; 4432.13,3021.01 4459.76,3034.82 4487.39,3021.01 4473.58,3048.64 4487.39,3076.27 4459.76,3062.45 4432.13,3076.27 4445.95,3048.64 4432.13,3021.01 ; 4432.13,3159.16 4445.95,3159.16 4459.76,3145.34 4473.58,3159.16 4487.39,3159.16 4473.58,3172.97 4487.39,3186.79 4473.58,3186.79 4459.76,3200.6 4445.95,3186.79 4432.13,3186.79 4445.95,3172.97 4432.13,3159.16
  lines w12: 4382.04,2486.36 7612.09,2486.36 ; 4382.04,3232.38 7612.09,3232.38 ; 4719.78,2362.03 4719.78,3356.71 ; 5051.6,2362.03 5051.6,3356.71 ; 5687.7,2362.03 5687.7,3356.71 ; 5946.7,2362.03 5946.7,3356.71 ; 6321.67,2362.03 6321.67,3356.71 ; 7045.9,2362.03 7045.9,3356.71 ; 4382.04,2362.03 7612.09,2362.03 7612.09,3356.71 4382.04,3356.71 4382.04,2362.03
  text "Symbol" at 4456.64,3269.68 h72
  text "Quantity" at 4757.08,3269.68 h72
  text "Finished Hole Size" at 5088.9,3269.68 h72
  text "Plated" at 5725,3269.68 h72
  text "Hole Type" at 5984,3269.68 h72
  text "Drill Layer Pair" at 6358.97,3269.68 h72
  text "Hole Tolerance" at 7083.2,3269.68 h72
  text "4" at 4757.08,3145.34 h60
  text "7.87mil (0.200mm)" at 5088.9,3145.34 h60
  text "PTH" at 5725,3145.34 h60
  text "Round" at 5984,3145.34 h60
  text "Top Layer - Bottom Layer" at 6358.97,3145.34 h60
  text "156" at 4757.08,3021.01 h60
  text "8.00mil (0.203mm)" at 5088.9,3021.01 h60
  text "PTH" at 5725,3021.01 h60
  text "Round" at 5984,3021.01 h60
  text "Top Layer - Bottom Layer" at 6358.97,3021.01 h60
  text "70" at 4757.08,2896.67 h60
  text "10.00mil (0.254mm)" at 5088.9,2896.67 h60
  text "PTH" at 5725,2896.67 h60
  text "Round" at 5984,2896.67 h60
  text "Top Layer - Bottom Layer" at 6358.97,2896.67 h60
  text "3" at 4757.08,2772.34 h60
  text "40.00mil (1.016mm)" at 5088.9,2772.34 h60
  text "PTH" at 5725,2772.34 h60
  text "Round" at 5984,2772.34 h60
  text "Top Layer - Bottom Layer" at 6358.97,2772.34 h60
  text "19" at 4757.08,2648 h60
  text "63.00mil (1.600mm)" at 5088.9,2648 h60
  text "PTH" at 5725,2648 h60
  text "Round" at 5984,2648 h60
  text "Top Layer - Bottom Layer" at 6358.97,2648 h60
  text "4" at 4757.08,2523.66 h60
  text "125.98mil (3.200mm)" at 5088.9,2523.66 h60
  text "PTH" at 5725,2523.66 h60
  text "Round" at 5984,2523.66 h60
  text "Top Layer - Bottom Layer" at 6358.97,2523.66 h60
  text "256 Total" at 4757.08,2399.33 h60
  text ".Layer_Name" at 277,-928.49 h60
M17 Embedded Cavity:
  text ".Layer_Name" at 277,-928.49 h60
M18 Embedded Assembly:
  text ".Layer_Name" at 277,-928.49 h60
M19 Embedded Keepout:
  text ".Layer_Name" at 277,-928.49 h60

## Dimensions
-300,-470 to 700,-470 on M2 Board Dimensions
0,0 to 0,2500 on M2 Board Dimensions
0,0 to 3500,0 on M2 Board Dimensions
